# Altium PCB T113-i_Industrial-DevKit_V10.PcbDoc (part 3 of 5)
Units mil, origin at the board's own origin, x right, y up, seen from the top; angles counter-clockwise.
Board outline 4212.61 x 3188.98 mil, 4 copper layers (Top Layer, GND, PWR, Bottom Layer); 249 components, 236 nets, 911 pads, 571 vias.
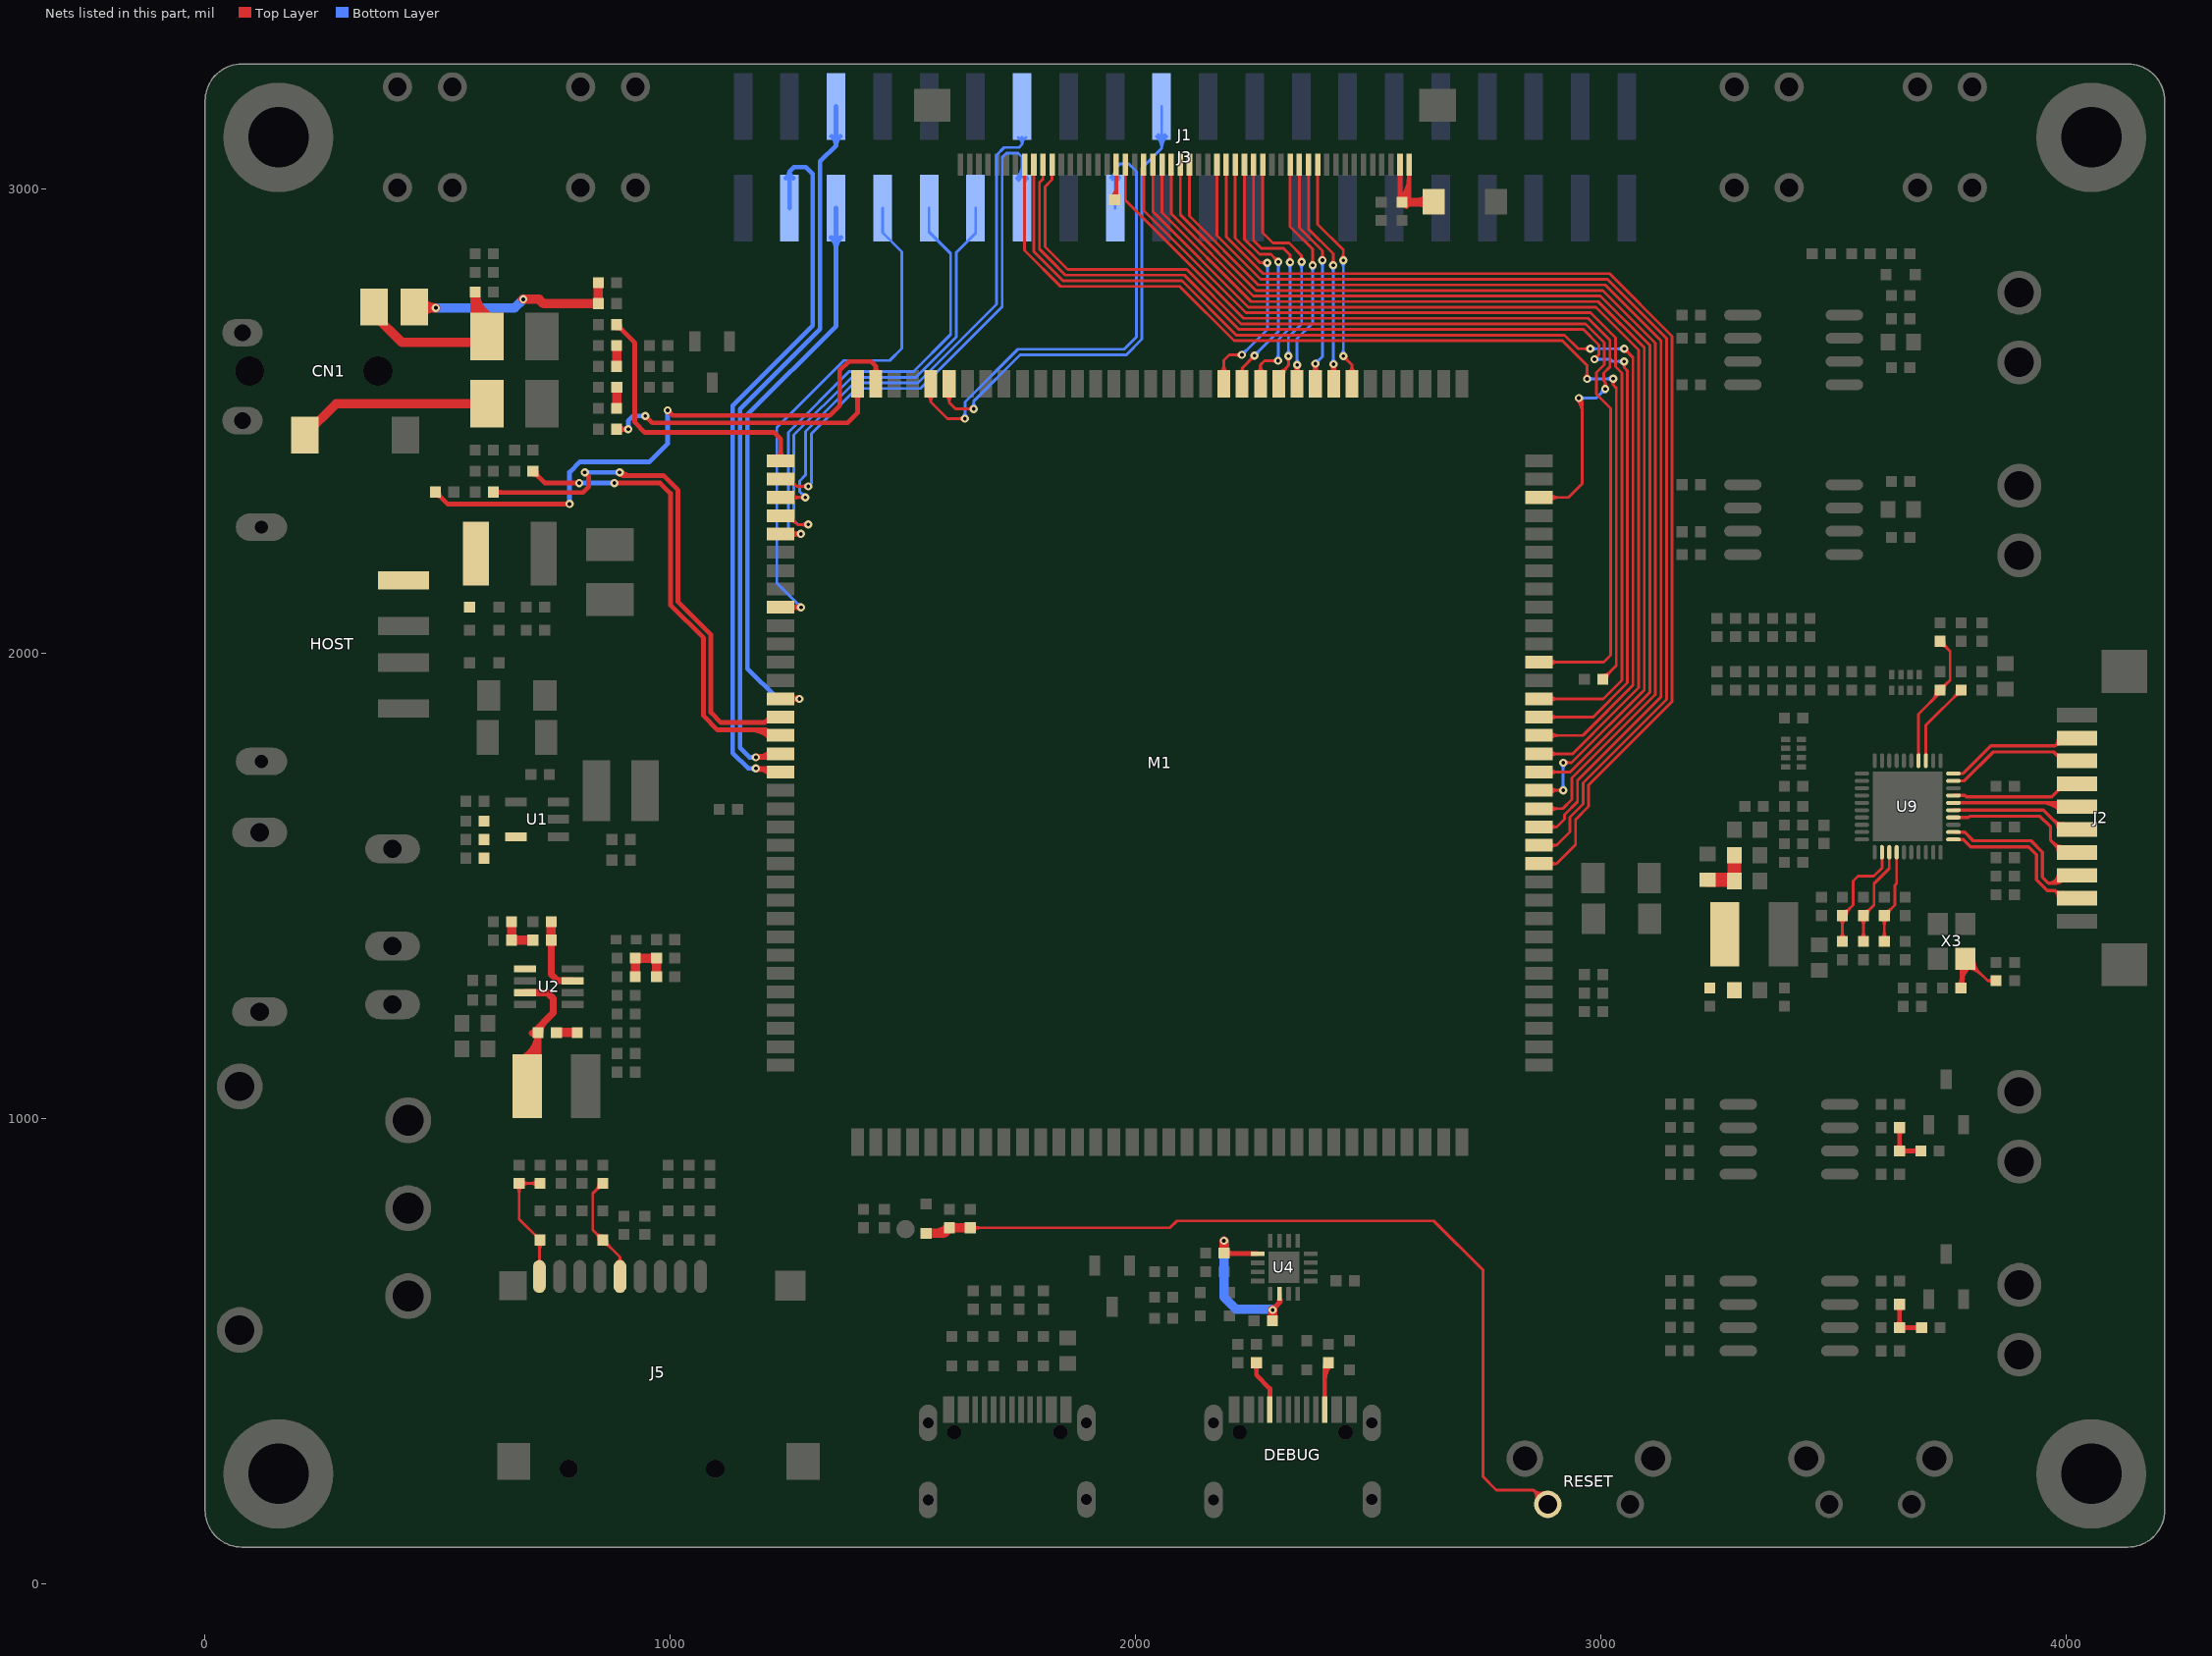
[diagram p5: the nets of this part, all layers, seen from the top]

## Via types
v1: diameter 17.72, hole 7.87, Top Layer to Bottom Layer, tented both sides, 571 vias

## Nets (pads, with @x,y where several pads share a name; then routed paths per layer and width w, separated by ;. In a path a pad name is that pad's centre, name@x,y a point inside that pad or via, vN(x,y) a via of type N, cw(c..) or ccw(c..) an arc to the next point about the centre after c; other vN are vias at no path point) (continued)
LCD_D4: J1.11 M1.109 | length 640.3
  Top Layer w6: J1.11@2389.68,3031.25 cw(c2384.72,3026.29) 2391.73,3026.29 cw(c2398.75,3026.29) J1.11@2393.79,3031.25 ; J1.11@2391.73,3051.03 2391.73,2923.2 2446.78,2868.16 v1(2446.78,2845.7) ; v1@2442.63,2849.84 ccw(c2432.63,2859.84) 2446.78,2859.84 ccw(c2460.92,2859.84) v1@2450.92,2849.84 ; v1@2446.73,2633.78 cw(c2446.73,2619.63) 2456.73,2629.64 cw(c2466.73,2639.64) v1@2452.58,2639.64 ; v1(2446.73,2639.64) 2465.55,2620.81 ; M1.109@2458.12,2603.48 ccw(c2441.63,2620.81) 2465.55,2620.81 ; M1.109@2465.55,2579.92 2465.55,2620.81 ; M1.109@2472.98,2603.48 cw(c2489.48,2620.81) 2465.55,2620.81
  Bottom Layer w6: v1@2442.58,2643.78 ccw(c2432.46,2653.9) 2446.78,2653.9 ; v1@2442.63,2841.56 cw(c2432.63,2831.56) 2446.78,2831.56 cw(c2460.92,2831.56) v1@2450.92,2841.56 ; v1@2446.78,2639.64 v1(2446.78,2845.7) ; 2446.78,2653.66 ccw(c2460.75,2653.66) v1@2450.87,2643.78
LCD_D5: J1.12 M1.110 | length 674.1
  Top Layer w6: J1.12@2369.99,3031.25 cw(c2365.03,3026.29) 2372.04,3026.29 cw(c2379.06,3026.29) J1.12@2374.1,3031.25 ; J1.12@2372.04,3051.03 2372.04,2912.65 2425.09,2859.61 v1(2425.09,2835.03) ; M1.110@2418.56,2603.29 ccw(c2401.65,2620.2) v1@2425.56,2620.2 ; v1@2420.81,2618.97 cw(c2411.44,2612.19) M1.110@2422.61,2609.2 ; v1@2420.94,2839.18 ccw(c2410.94,2849.18) 2425.09,2849.18 ccw(c2439.23,2849.18) v1@2429.23,2839.18 ; v1@2421.42,2618.26 cw(c2411.42,2608.26) 2425.56,2608.26 cw(c2439.7,2608.26) v1@2429.7,2618.26 ; v1@2422.78,2617.25 cw(c2416.67,2605.94) 2429.08,2609.27 cw(c2441.49,2612.6) v1@2430.55,2619.33 ; 2422.81,2609.93 cw(c2434.59,2606.77) v1@2428.49,2617.33 ; M1.110@2426.18,2579.92 2425.56,2580.54 v1(2425.56,2622.41) ccw(c2451.83,2622.4) M1.110@2433.64,2603.45
  Bottom Layer w6: v1@2420.94,2830.89 cw(c2410.94,2820.89) 2425.09,2820.89 cw(c2439.23,2820.89) v1@2429.23,2830.89 ; v1@2421.42,2626.55 ccw(c2412.56,2635.4) 2425.09,2635.4 ; 2425.09,2637.69 ccw(c2440.85,2637.69) v1@2429.7,2626.55 ; v1(2425.09,2835.03) 2425.09,2622.88 v1(2425.56,2622.41)
LCD_D6: J1.13 M1.111 | length 674.1
  Top Layer w6: J1.13@2350.31,3031.25 cw(c2345.35,3026.29) 2352.36,3026.29 cw(c2359.38,3026.29) J1.13@2354.42,3031.25 ; J1.13@2352.36,3051.03 2352.36,2915.36 2401.86,2865.87 v1(2401.86,2845.86) v1@2401.86,2844.16 ; M1.111@2379.19,2603.29 ccw(c2360.79,2621.69) 2386.81,2621.69 ccw(c2412.84,2621.69) M1.111@2394.43,2603.29 ; v1@2381.82,2620.06 cw(c2371.25,2612.92) 2383.57,2609.62 ; v1@2382.53,2619.2 cw(c2372.21,2608.87) M1.111@2386.81,2608.87 ; v1@2383.75,2618.27 cw(c2377.18,2606.9) 2389.86,2610.3 ; 2383.9,2610.84 cw(c2395.72,2607.67) v1@2389.61,2618.27 ; M1.111@2386.81,2588.63 v1@2386.81,2623.34 ; 2386.81,2609.53 cw(c2400.49,2609.53) v1@2390.82,2619.2 ; M1.111@2390.16,2609.18 cw(c2404.17,2612.93) v1@2391.71,2620.35 ; v1@2397.71,2850 ccw(c2387.71,2860) 2401.86,2860 ccw(c2416,2860) v1@2406,2850
  Bottom Layer w6: v1(2386.68,2623.34) 2401.86,2638.52 v1(2401.86,2845.86) ; v1@2386.68,2629.2 ccw(c2386.68,2643.35) 2396.68,2633.34 ccw(c2406.68,2623.34) v1@2392.53,2623.34 ; v1@2397.71,2841.72 cw(c2387.71,2831.71) 2401.86,2831.71 cw(c2416,2831.71) v1@2406,2841.72
LCD_D7: J1.14 M1.112 | length 678
  Top Layer w6: J1.14@2330.62,3031.25 cw(c2325.66,3026.29) 2332.67,3026.29 cw(c2339.69,3026.29) J1.14@2334.73,3031.25 ; J1.14@2332.67,3051.03 2332.67,2918.08 2380.88,2869.88 v1(2380.88,2834.8) ; M1.112@2340.06,2603.52 ccw(c2323.98,2620.63) v1(2347.45,2620.63) ; v1@2342.74,2617.14 cw(c2334.97,2611.39) 2344.31,2608.89 cw(c2353.65,2606.39) v1@2349.79,2615.26 ; v1@2343.31,2616.48 cw(c2333.31,2606.48) 2347.45,2606.48 cw(c2361.6,2606.48) v1@2351.6,2616.48 ; v1@2345.11,2615.26 cw(c2341.21,2606.34) 2350.61,2608.86 cw(c2360,2611.38) v1@2352.17,2617.15 ; M1.112@2347.44,2579.92 v1(2347.45,2620.63) ; M1.112@2354.84,2603.51 cw(c2370.98,2620.63) v1(2347.45,2620.63) ; v1@2376.73,2838.94 ccw(c2366.73,2848.94) 2380.88,2848.94 ccw(c2395.02,2848.94) v1@2385.02,2838.94
  Bottom Layer w6: v1@2343.31,2624.77 ccw(c2333.31,2634.77) 2347.45,2634.77 ccw(c2361.6,2634.77) v1@2351.6,2624.77 ; v1(2347.45,2620.63) 2347.45,2676.92 2380.88,2710.35 v1(2380.88,2834.8) ; v1@2376.73,2830.65 cw(c2366.73,2820.65) 2380.88,2820.65 cw(c2395.02,2820.65) v1@2385.02,2830.65
LCD_D10: J1.17 M1.113 | length 680
  Top Layer w6: J1.17@2271.57,3031.25 cw(c2266.61,3026.29) 2273.62,3026.29 cw(c2280.64,3026.29) J1.17@2275.68,3031.25 ; J1.17@2273.62,3051.03 2273.62,2905.07 2295.39,2883.3 2330,2883.3 2357.05,2856.25 ; M1.113@2308.07,2606.18 2315.24,2606.18 2328.97,2619.91 2328.97,2643.76 v1@2328.87,2643.87 ; M1.113@2308.07,2606.45 ccw(c2308.07,2624.4) 2320.76,2611.71 ; M1.113@2312.85,2595.67 cw(c2332.46,2595.67) 2318.59,2609.54 ; M1.113@2318.85,2595.67 cw(c2352.95,2595.67) 2328.84,2619.78 ; v1@2324.72,2635.86 cw(c2314.47,2625.6) 2328.97,2625.6 ; 2328.97,2626.11 cw(c2342.76,2626.11) v1@2333.01,2635.86 ; v1@2352.95,2846.44 ccw(c2343.29,2856.25) 2357.06,2856.25 ; v1(2357.05,2842.26) 2357.05,2856.25 ; v1@2361.16,2846.44 cw(c2370.82,2856.25) 2357.05,2856.25
  Bottom Layer w6: v1@2324.72,2644.14 ccw(c2314.72,2654.14) 2328.87,2654.14 ccw(c2343.01,2654.14) v1@2333.01,2644.14 ; v1@2328.87,2643.87 2328.87,2680.15 2357.05,2708.33 v1(2357.05,2842.26) ; v1@2352.91,2838.12 cw(c2342.91,2828.12) 2357.05,2828.12 cw(c2371.2,2828.12) v1@2361.2,2838.12
  other v1: 2328.87,2640
LCD_D11: J1.18 M1.114 | length 694.4
  Top Layer w6: J1.18@2251.88,3031.25 cw(c2246.92,3026.29) 2253.93,3026.29 cw(c2260.95,3026.29) J1.18@2255.99,3031.25 ; J1.18@2253.93,3051.03 2253.93,2888.2 2270.84,2871.3 2318.06,2871.3 2332.28,2857.08 v1(2332.28,2841.55) ; M1.114@2261.26,2603.47 ccw(c2244.65,2620.86) 2268.7,2620.86 ; M1.114@2268.7,2598.96 2268.7,2620.86 ; M1.114@2276.14,2603.47 cw(c2292.75,2620.86) 2268.7,2620.86 ; v1@2302.62,2625.52 ccw(c2292.62,2615.52) 2292.62,2629.66 ccw(c2292.62,2643.8) v1@2302.62,2633.8 ; v1(2306.76,2629.66) 2277.5,2629.66 2268.7,2620.86 ; v1@2328.14,2845.69 ccw(c2318.14,2855.69) 2332.28,2855.69 ccw(c2346.43,2855.69) v1@2336.43,2845.69
  Bottom Layer w6: v1@2302.62,2633.8 ccw(c2292.62,2643.8) 2306.76,2643.8 ccw(c2320.9,2643.8) v1@2310.9,2633.8 ; v1(2306.76,2629.66) 2306.76,2648.59 2306.76,2675.01 2332.28,2700.53 v1(2332.28,2841.55) ; v1@2328.14,2837.41 cw(c2318.14,2827.41) 2332.28,2827.41 cw(c2346.43,2827.41) v1@2336.43,2837.41
LCD_D12: J1.19 M1.115 | length 653
  Top Layer w6: M1.115@2224.19,2605.14 ccw(c2219.09,2614.52) 2229.76,2614.52 ; M1.115@2229.76,2597.7 2229.76,2614.52 ; J1.19@2232.2,3031.25 cw(c2227.24,3026.29) 2234.25,3026.29 cw(c2241.27,3026.29) J1.19@2236.31,3031.25 ; J1.19@2234.25,3051.03 2234.25,2890.91 2266.67,2858.5 2291.27,2858.5 v1(2307.18,2842.59) ; M1.115@2235.12,2604.76 cw(c2241.32,2614.52) 2229.76,2614.52 ; v1@2250.16,2640.77 cw(c2236.01,2640.77) 2246.01,2630.77 cw(c2256.01,2620.77) v1@2256.01,2634.91 ; v1(2256.01,2640.77) 2229.76,2614.52 ; v1@2301.32,2842.59 ccw(c2287.18,2842.59) 2297.18,2852.59 ccw(c2307.18,2862.59) v1@2307.18,2848.45
  Bottom Layer w6: v1(2256.01,2640.77) 2256.01,2641.24 2307.18,2692.4 v1(2307.18,2842.59) ; v1@2256.01,2646.63 ccw(c2256.01,2659.65) 2265.22,2650.45 ; v1@2261.87,2640.77 cw(c2277.13,2640.77) 2266.34,2651.56 ; v1@2303.04,2838.45 cw(c2293.04,2828.45) 2307.18,2828.45 cw(c2321.33,2828.45) v1@2311.33,2838.45
LCD_D13: J1.20 M1.116 | length 704.4
  Top Layer w6: M1.116@2182.34,2603.29 ccw(c2163.94,2621.69) 2189.96,2621.69 ccw(c2215.98,2621.69) M1.116@2197.58,2603.29 ; M1.116@2189.96,2579.92 2189.96,2630.85 2201.49,2642.38 v1(2228.75,2642.38) ; J1.20@2212.51,3031.25 cw(c2207.55,3026.29) 2214.56,3026.29 cw(c2221.58,3026.29) J1.20@2216.62,3031.25 ; J1.20@2214.56,3051.03 2214.56,2893.63 2267.83,2840.37 v1(2283.57,2840.37) ; v1@2224.61,2638.23 ccw(c2214.61,2628.23) 2214.61,2642.38 ccw(c2214.61,2656.52) v1@2224.61,2646.52 ; v1@2279.43,2836.22 ccw(c2269.43,2826.22) 2269.43,2840.37 ccw(c2269.43,2854.51) v1@2279.43,2844.51
  Bottom Layer w6: v1(2228.75,2642.38) 2283.57,2697.19 v1(2283.57,2840.37) ; v1@2228.75,2648.23 ccw(c2228.75,2662.38) 2238.75,2652.38 ccw(c2248.75,2642.38) v1@2234.61,2642.38 ; v1@2279.43,2836.22 cw(c2269.43,2826.22) 2283.57,2826.22 cw(c2297.71,2826.22) v1@2287.71,2836.22
LCD_D14: J1.21 M1.80 | length 2521.4
  Top Layer w6: J1.21@2192.83,3031.25 cw(c2187.87,3026.29) 2194.88,3026.29 cw(c2201.9,3026.29) J1.21@2196.94,3031.25 ; J1.21@2194.88,3051.03 2194.88,2896.34 2274.3,2816.92 3019.57,2816.92 3153.75,2682.74 3153.75,1896.79 2974.43,1717.46 2974.43,1671.5 2946.17,1643.24 2946.17,1589.02 2905.58,1548.43 ; M1.80@2867.13,1548.43 2905.58,1548.43 ; M1.80@2891.23,1541.61 cw(c2905.57,1529.91) 2905.57,1548.43 ; M1.80@2891.23,1555.24 ccw(c2905.57,1566.94) 2905.57,1548.43
LCD_D15: J1.22 M1.81 | length 2480.4
  Top Layer w6: J1.22@2173.14,3031.25 cw(c2168.18,3026.29) 2175.19,3026.29 cw(c2182.21,3026.29) J1.22@2177.25,3031.25 ; J1.22@2175.19,3051.03 2175.19,2898.84 2269.12,2804.92 3014.6,2804.92 3141.75,2677.77 3141.75,1901.76 2962.43,1722.43 2962.43,1676.47 2934.17,1648.21 2934.17,1616.39 2905.58,1587.8 ; M1.81@2867.13,1587.8 2905.58,1587.8 ; M1.81@2891.23,1580.98 cw(c2905.57,1569.28) 2905.57,1587.8 ; M1.81@2891.23,1594.61 ccw(c2905.57,1606.31) 2905.57,1587.8
LCD_D18: J1.25 M1.82 | length 2455.9
  Top Layer w6: J1.25@2114.09,3031.25 cw(c2109.13,3026.29) 2116.14,3026.29 cw(c2123.16,3026.29) J1.25@2118.2,3031.25 ; J1.25@2116.14,3051.03 2116.14,2940.92 2264.14,2792.92 3009.63,2792.92 3129.75,2672.8 3129.75,1906.73 2950.43,1727.4 2950.43,1681.44 2922.17,1653.18 2922.17,1643.65 2905.68,1627.17 ; M1.82@2867.13,1627.17 2905.68,1627.17 ; M1.82@2891.2,1620.32 cw(c2905.68,1608.42) 2905.68,1627.17 ; M1.82@2891.2,1634.01 ccw(c2905.68,1645.91) 2905.68,1627.17
LCD_D19: J1.26 M1.83 | length 2430.1
  Top Layer w6: J1.26@2094.4,3031.25 cw(c2089.44,3026.29) 2096.45,3026.29 cw(c2103.47,3026.29) J1.26@2098.51,3031.25 ; J1.26@2096.45,3051.03 2096.45,2943.57 2259.1,2780.92 3004.66,2780.92 3117.75,2667.83 3117.75,1911.7 2938.43,1732.37 2938.43,1686.41 2918.55,1666.54 M1.83@2867.13,1666.54 ; M1.83@2890.5,1658.91 cw(c2908.9,1640.51) 2908.9,1666.54 cw(c2908.9,1692.56) M1.83@2890.5,1674.16
LCD_D20: J1.27 M1.85 | length 2359.2
  Top Layer w6: J1.27@2074.72,3031.25 cw(c2069.76,3026.29) 2076.77,3026.29 cw(c2083.79,3026.29) J1.27@2078.83,3031.25 ; J1.27@2076.77,3051.03 2076.77,2945.69 2253.54,2768.92 2999.69,2768.92 3105.75,2662.86 3105.75,1916.67 2934.36,1745.28 M1.85@2867.13,1745.28 ; M1.85@2890.5,1737.65 cw(c2908.9,1719.25) 2908.9,1745.28 cw(c2908.9,1771.3) M1.85@2890.5,1752.9
LCD_D21: J1.28 M1.84 | length 2487.4
  Top Layer w6: J1.28@2055.03,3031.25 cw(c2050.07,3026.29) 2057.08,3026.29 cw(c2064.1,3026.29) J1.28@2059.14,3031.25 ; J1.28@2057.08,3051.03 2057.08,2948.21 2248.37,2756.92 2994.72,2756.92 3093.75,2657.89 3093.75,1921.64 2937.48,1765.37 v1(2919.56,1765.37) ; M1.84@2867.13,1705.91 2867.33,1706.11 v1(2919.56,1706.11) ; M1.84@2890.5,1698.28 cw(c2909.39,1679.39) 2909.39,1706.11 ; M1.84@2890.5,1713.53 ccw(c2908.4,1731.43) 2908.4,1706.11 ; v1@2915.42,1701.97 ccw(c2905.41,1691.96) 2905.41,1706.11 ccw(c2905.42,1720.25) v1@2915.42,1710.25 ; v1@2923.7,1761.23 cw(c2933.7,1751.23) 2933.7,1765.37 cw(c2933.7,1779.51) v1@2923.7,1769.51
  Bottom Layer w6: v1@2915.42,1710.25 ccw(c2905.42,1720.25) 2919.56,1720.25 ccw(c2933.7,1720.25) v1@2923.7,1710.25 ; v1@2915.42,1761.23 cw(c2905.42,1751.23) 2919.56,1751.23 cw(c2933.7,1751.23) v1@2923.7,1761.23 ; v1(2919.56,1706.11) v1(2919.56,1765.37)
LCD_D22: J1.29 M1.86 | length 2319.9
  Top Layer w6: J1.29@2035.35,3031.25 cw(c2030.39,3026.29) 2037.4,3026.29 cw(c2044.42,3026.29) J1.29@2039.46,3031.25 ; J1.29@2037.4,3051.03 2037.4,2950.23 2242.71,2744.92 2989.74,2744.92 3081.75,2652.92 3081.75,1926.73 3030.98,1875.96 3030.98,1875.84 2939.79,1784.65 M1.86@2867.13,1784.65 ; M1.86@2890.5,1777.02 cw(c2908.9,1758.62) 2908.9,1784.65 cw(c2908.9,1810.67) M1.86@2890.5,1792.27
LCD_D23: J1.30 M1.89 | length 2214.9
  Top Layer w6: J1.30@2015.66,3031.25 cw(c2010.7,3026.29) 2017.71,3026.29 cw(c2024.73,3026.29) J1.30@2019.77,3031.25 ; J1.30@2017.71,3051.03 2017.71,2952.86 2237.65,2732.92 2978.17,2732.92 3032.07,2679.03 3032.07,2616.83 3045.75,2603.15 3045.75,1942.84 3005.67,1902.76 M1.89@2867.13,1902.76 ; M1.89@2890.5,1895.13 cw(c2908.9,1876.73) 2908.9,1902.76 cw(c2908.9,1928.78) M1.89@2890.5,1910.38
LCD_DE: J1.40 M1.91 | length 2375.1
  Top Layer w6: J1.40@1818.81,3031.25 cw(c1813.85,3026.29) 1820.86,3026.29 cw(c1827.88,3026.29) J1.40@1822.92,3031.25 ; J1.40@1820.86,3051.03 1820.86,3019.12 1805.49,3003.74 1805.49,2874.84 1854.42,2825.91 2110.15,2825.91 2227.13,2708.92 2968.02,2708.92 3008.07,2668.87 3008.07,2621.33 2991.15,2604.41 2991.15,2557.81 3021.75,2527.21 3021.75,1996.75 3006.5,1981.5 M1.91@2867.13,1981.5 ; M1.91@2890.5,1973.87 cw(c2908.9,1955.47) 2908.9,1981.5 cw(c2908.9,2007.52) M1.91@2890.5,1989.12
LCD_HSYNC: J1.42 M1.87 | length 2662
  Top Layer w6: J1.42@1779.44,3031.25 cw(c1774.48,3026.29) 1781.49,3026.29 cw(c1788.51,3026.29) J1.42@1783.55,3031.25 ; J1.42@1781.49,3051.03 1781.49,2864.56 1844.15,2801.91 2100.02,2801.91 2217,2684.92 2922.61,2684.92 2952.06,2655.47 v1(2977.64,2655.47) ; M1.87@2867.13,1824.02 2961.95,1824.02 3069.75,1931.81 3069.75,2636.72 v1(3051,2655.47) ; M1.87@2890.5,1816.39 cw(c2908.9,1797.99) 2908.9,1824.02 cw(c2908.9,1850.04) M1.87@2890.5,1831.64 ; v1@2973.49,2651.33 ccw(c2963.49,2641.33) 2963.49,2655.47 ccw(c2963.49,2669.61) v1@2973.49,2659.61 ; v1@3051,2649.61 cw(c3051,2635.47) 3061,2645.47 cw(c3071,2655.47) v1@3056.86,2655.47
  Bottom Layer w6: v1(2977.64,2655.47) v1(3051,2655.47) ; v1@2981.78,2651.33 cw(c2991.78,2641.33) 2991.78,2655.47 cw(c2991.78,2669.61) v1@2981.78,2659.61 ; v1@3046.86,2651.33 ccw(c3036.86,2641.33) 3036.86,2655.47 ccw(c3036.86,2669.61) v1@3046.86,2659.61
LCD_PCLK: J1.43 R67.1 | length 2378.5
  Top Layer w6: J1.43@1759.76,3031.25 cw(c1754.8,3026.29) 1761.81,3026.29 cw(c1768.83,3026.29) J1.43@1763.87,3031.25 ; J1.43@1761.81,3051.03 1761.81,2867 1839.05,2789.76 2095.19,2789.76 2212.03,2672.92 2917.64,2672.92 2970.87,2619.69 v1(2970.87,2590.63) ; v1@2966.73,2594.77 ccw(c2956.73,2604.77) 2970.87,2604.77 ccw(c2985.01,2604.77) v1@2975.01,2594.77 ; R67.1@3004.68,1945 3033.75,1974.07 3033.75,2571.21 3027,2577.96 ; R67.1@3004.68,1953.81 ccw(c3004.68,1975.08) 3019.73,1960.04 ccw(c3034.77,1945) R67.1@3013.5,1945 ; v1@3022.68,2591 v1@3027,2586.67 ; v1@3023.11,2586.62 cw(c3015.42,2577.96) 3027,2577.96 ; v1(3027,2591) v1@3027,2586.67 ; v1@3030.89,2586.62 ccw(c3038.58,2577.96) 3027,2577.96 ; 3027,2577.96 v1@3027,2586.67
  Bottom Layer w6: v1@2970.77,2590.63 v1(2970.87,2590.63) 2971.24,2591 v1(3027,2591) ; v1@2975.01,2586.49 cw(c2985.89,2575.61) 2985.89,2591 ; v1@2975.01,2594.77 ccw(c2984.14,2603.9) 2984.14,2591 ; v1@3022.86,2586.85 ccw(c3012.86,2576.85) 3012.86,2591 ccw(c3012.86,2605.14) v1@3022.86,2595.14
LCD_PWM: J1.32 M1.100 | length 1892.4
  Top Layer w6: J1.32@1976.29,3031.25 cw(c1971.33,3026.29) 1978.34,3026.29 cw(c1985.36,3026.29) J1.32@1980.4,3031.25 ; J1.32@1978.34,3051.03 1978.34,2974.68 2232.11,2720.92 2973.11,2720.92 3020.07,2673.96 3020.07,2616.36 3006.75,2603.04 3006.75,2586.09 3010,2582.84 ; M1.100@2867.13,2335.83 2931.07,2335.83 2960.42,2365.18 2960.42,2542.19 ; M1.100@2890.5,2328.21 cw(c2908.9,2309.8) 2908.9,2335.83 cw(c2908.9,2361.85) M1.100@2890.5,2343.45 ; v1@2949.02,2545.31 cw(c2921.49,2517.78) 2960.42,2517.78 ; v1(2953.16,2549.45) 2960.42,2542.19 ; v1@2953.26,2549.55 cw(c2935.98,2532.27) 2960.42,2532.27 ; v1@2954.62,2543.78 cw(c2956.13,2537.9) 2960.42,2542.19 ; v1@2958.83,2548 ccw(c2964.71,2546.48) 2960.42,2542.19 ; v1@3005.91,2573.16 ccw(c2996.49,2582.84) 3010,2582.84 ; v1(3010,2568.96) 3010,2582.84 ; v1@3014.09,2573.16 cw(c3023.51,2582.84) 3010,2582.84
  Bottom Layer w6: v1(2953.16,2549.45) 2990.49,2549.45 v1(3010,2568.96) ; v1@2957.3,2545.31 cw(c2967.3,2535.31) 2967.3,2549.45 cw(c2967.3,2563.6) v1@2957.3,2553.6 ; v1@3004.14,2568.96 cw(c2990,2568.96) 3000,2558.96 cw(c3010,2548.96) v1@3010,2563.1
LCD_RESET: J1.33 R70.2 | length 101.2
  Top Layer w8: R70.2@1949.48,2981.47 ccw(c1927.3,3003.65) 1958.66,3003.65 ; R70.2@1955,2975.94 1958.66,2979.61 J1.33@1958.66,3051.03
LCD_VSYNC: J1.41 M1.88 | length 2624.4
  Top Layer w6: J1.41@1799.13,3031.25 cw(c1794.17,3026.29) 1801.18,3026.29 cw(c1808.2,3026.29) J1.41@1803.24,3031.25 ; J1.41@1801.18,3051.03 1801.18,3020.43 1793.49,3012.74 1793.49,2869.87 1832.55,2830.81 ; 1832.39,2830.64 1849.12,2813.91 2104.99,2813.91 2221.97,2696.92 2962.91,2696.92 2996.07,2663.77 2996.07,2642.26 ; M1.88@2867.13,1863.39 2983.95,1863.39 3057.75,1937.18 3057.75,2608.12 3050.88,2614.99 ; M1.88@2890.5,1855.76 cw(c2908.9,1837.36) 2908.9,1863.39 cw(c2908.9,1889.41) M1.88@2890.5,1871.01 ; v1(2986.76,2632.95) 2996.07,2642.26 ; v1@2987.07,2638.8 ccw(c2987.68,2650.65) 2996.07,2642.26 ; v1@2992.61,2633.26 cw(c3004.45,2633.88) 2996.07,2642.26 ; v1@3046.95,2623.87 cw(c3038.9,2614.99) 3050.88,2614.99 ; v1(3050.88,2628.21) 3050.88,2614.99 ; v1@3054.82,2623.87 ccw(c3062.87,2614.99) 3050.88,2614.99
  Bottom Layer w6: v1(2986.76,2632.95) 3021.61,2632.95 3026.35,2628.21 v1(3050.88,2628.21) ; v1@2990.9,2628.81 cw(c3000.9,2618.81) 3000.9,2632.95 cw(c3000.9,2647.1) v1@2990.9,2637.1 ; v1@3046.74,2624.07 ccw(c3036.74,2614.07) 3036.74,2628.21 ccw(c3036.74,2642.35) v1@3046.74,2632.35
LED0/CFG_EXT: R97.1 R103.2 U9.32 | length 347.2
  Top Layer w6: R97.1@3513.77,1387.18 ccw(c3498.73,1402.22) 3520,1402.22 ccw(c3541.27,1402.22) R97.1@3526.23,1387.18 ; R103.2@3513.77,1430.34 cw(c3498.73,1415.3) 3520,1415.3 cw(c3541.27,1415.3) R103.2@3526.23,1430.34 ; R97.1@3520,1380.94 R103.2@3520,1436.57 3542.6,1459.17 3542.6,1510.72 3553.41,1521.53 3587.3,1521.53 3604.9,1539.13 U9.32@3604.9,1572.86 ; R103.2@3520,1445.39 ccw(c3520,1466.66) 3535.04,1451.62 ccw(c3550.08,1436.57) R103.2@3528.81,1436.57
LED1/CFG_LDO0: R96.1 R102.2 U9.33 | length 315.2
  Top Layer w6: R96.1@3558.77,1387.18 ccw(c3543.73,1402.22) 3565,1402.22 ccw(c3586.27,1402.22) R96.1@3571.23,1387.18 ; R102.2@3558.77,1430.34 cw(c3543.73,1415.3) 3565,1415.3 cw(c3586.27,1415.3) R102.2@3571.23,1430.34 ; R96.1@3565,1380.94 R102.2@3565,1436.57 3587.93,1459.51 3587.93,1505.19 3620.6,1537.86 U9.33@3620.6,1572.86 ; R102.2@3565,1445.39 ccw(c3565,1466.66) 3580.04,1451.62 ccw(c3595.08,1436.57) R102.2@3573.81,1436.57
LED2/CFG_LDO1: R95.1 R101.2 U9.34 | length 303.1
  Top Layer w6: R95.1@3603.77,1387.18 ccw(c3588.73,1402.22) 3610,1402.22 ccw(c3631.27,1402.22) R95.1@3616.23,1387.18 ; R101.2@3603.77,1430.34 cw(c3588.73,1415.3) 3610,1415.3 cw(c3631.27,1415.3) R101.2@3616.23,1430.34 ; R95.1@3610,1380.94 R101.2@3610,1436.57 3632.58,1459.15 3632.58,1501.97 3636.4,1505.8 U9.34@3636.4,1572.86 ; R101.2@3610,1445.39 ccw(c3610,1466.66) 3625.04,1451.62 ccw(c3640.08,1436.57) R101.2@3618.81,1436.57
LINEINL: C26.1 M1.1 | length 661
  Top Layer w10: C26.1@884.68,2700.67 cw(c884.68,2684.23) 896.31,2695.85 cw(c907.94,2707.48) C26.1@891.5,2707.48 ; C26.1@884.68,2707.48 923.72,2668.44 923.72,2497.02 945.26,2475.48 1223.34,2475.48 1237.2,2461.62 M1.1@1237.2,2414.57 ; M1.1@1231,2420.78 ccw(c1216.01,2435.76) 1237.2,2435.76 ccw(c1258.4,2435.76) M1.1@1243.41,2420.78
LINEINR: C27.1 M1.136 | length 743.9
  Top Layer w10: C27.1@884.68,2482.48 v1@909.62,2482.48 ; C27.1@889.5,2477.66 cw(c901.13,2466.04) 901.13,2482.48 cw(c901.13,2498.92) C27.1@889.5,2487.3 ; 896.57,2483.7 ccw(c899.94,2496.26) v1@907.42,2485.62 ; 896.61,2481.27 cw(c899.94,2468.84) v1@907.4,2479.33 ; 900.29,2482.48 cw(c900.29,2473.13) v1@906.91,2479.74 ; 900.35,2482.48 ccw(c900.35,2491.76) v1@906.91,2485.2 ; v1@946.06,2507.25 cw(c946.06,2497.93) 952.65,2504.52 cw(c959.23,2511.11) v1@949.92,2511.11 ; v1(946.06,2511.11) 960.95,2496.21 1381.43,2496.21 1402.56,2517.34 M1.136@1402.56,2565.66 ; M1.136@1396.35,2557.97 cw(c1381.36,2542.98) 1402.56,2542.98 cw(c1423.75,2542.98) M1.136@1408.77,2557.97
  Bottom Layer w10: v1@906.91,2485.2 ccw(c900.32,2491.78) 909.63,2491.78 ccw(c918.95,2491.78) v1@912.36,2485.2 ; v1(909.63,2482.47) 909.63,2500.45 920.29,2511.11 v1(946.06,2511.11) ; v1@943.33,2508.38 ccw(c936.75,2501.79) 936.75,2511.11 ccw(c936.75,2520.42) v1@943.33,2513.83
LINEOUTLN: J3.27 M1.2 | length 1280.4
  Top Layer w6: M1.2@1237.2,2375.2 1256.42,2375.2 1272.06,2359.56 ; M1.2@1255.12,2364.64 cw(c1258.88,2346.38) 1272.06,2359.56 ; M1.2@1263.73,2375.2 ccw(c1281.38,2375.2) 1268.9,2362.72 ; v1@1292.66,2355.42 ccw(c1282.66,2345.42) 1282.66,2359.56 ccw(c1282.66,2373.7) v1@1292.66,2363.7 ; v1(1296.8,2359.56) 1272.06,2359.56
  Bottom Layer w6: v1(1296.8,2359.56) 1303.09,2365.85 1303.09,2472.84 1400.4,2570.14 1537.69,2570.14 1713.49,2745.94 1713.49,3067.17 1722.73,3076.42 1747.63,3076.42 1756.3,3067.75 J3.27@1756.3,3025.53 ; J3.27@1744.22,3021.6 ccw(c1715.07,3050.75) 1756.3,3050.75 ccw(c1797.53,3050.75) J3.27@1768.38,3021.6 ; J3.27@1748.47,3017.36 ccw(c1729.55,3036.27) 1756.3,3036.27 ccw(c1783.05,3036.27) J3.27@1764.13,3017.36
LINEOUTLP: J3.28 M1.3 | length 1250.9
  Top Layer w6: M1.3@1237.2,2335.83 v1(1290.5,2335.85) ; M1.3@1260.57,2328.21 cw(c1279.03,2309.75) 1279.03,2335.85 ; M1.3@1260.57,2343.45 ccw(c1278.92,2361.8) 1278.92,2335.85 ; v1@1286.36,2331.71 ccw(c1276.36,2321.71) 1276.36,2335.85 ccw(c1276.36,2349.99) v1@1286.36,2339.99
  Bottom Layer w6: v1@1284.64,2335.85 ccw(c1270.5,2335.85) 1280.5,2345.85 ccw(c1290.5,2355.85) v1@1290.5,2341.71 ; v1(1290.5,2335.85) 1277.9,2348.45 1277.9,2371.01 1291.09,2384.2 1291.09,2424.99 1291.08,2477.89 1395.33,2582.14 1532.72,2582.14 1701.49,2750.91 1701.49,3072.14 1717.76,3088.42 1749.6,3088.42 1756.3,3095.12 ; J3.28@1747.85,3109.65 cw(c1739.58,3095.12) 1756.3,3095.12 ; J3.28@1756.3,3110.41 1756.3,3095.12 ; J3.28@1764.75,3109.65 ccw(c1773.02,3095.12) 1756.3,3095.12
LINEOUTRN: J3.29 M1.4 | length 1111.4
  Top Layer w6: M1.4@1237.2,2296.46 1254.87,2296.46 1273.79,2277.54 ; M1.4@1253.09,2291.68 cw(c1253.53,2276.94) M1.4@1263.96,2287.37 ; M1.4@1253.27,2285.68 cw(c1254.09,2257.84) 1273.79,2277.54 ; M1.4@1263.73,2296.46 ccw(c1285.14,2296.46) 1270,2281.32 ; v1@1292.31,2273.39 ccw(c1282.31,2263.39) 1282.31,2277.54 ccw(c1282.31,2291.68) v1@1292.31,2281.68 ; v1(1296.45,2277.54) 1273.79,2277.54
  Bottom Layer w6: 1265.5,2334.39 1265.5,2286.96 1274.93,2277.54 v1(1296.45,2277.54) ; 1265.64,2334.39 1265.64,2470.1 1389.69,2594.14 1527.75,2594.14 1614.67,2681.06 1614.67,2862.53 1656.3,2904.16 J3.29@1656.3,2957.75 ; v1@1292.31,2273.39 ccw(c1282.31,2263.39) 1282.31,2277.54 ccw(c1282.31,2291.68) v1@1292.31,2281.68
LINEOUTRP: J3.31 M1.5 | length 1137.7
  Top Layer w6: M1.5@1237.2,2257.09 1237.51,2257.39 v1(1280.87,2257.39) ; M1.5@1260.57,2249.46 cw(c1279.72,2230.32) v1@1279.72,2257.39 ; M1.5@1260.57,2264.71 ccw(c1278.24,2282.37) v1@1278.24,2257.39 ; M1.5@1266.68,2253.9 cw(c1270.45,2239.84) v1@1277.88,2252.36 ; 1266.89,2260.43 ccw(c1270.26,2273.02) v1@1277.58,2262.24 ; 1267.83,2254.21 ccw(c1264.43,2266.88) v1@1275.8,2260.32 ; 1268.62,2259.97 cw(c1265.57,2248.56) v1@1275.8,2254.46 ; v1@1276.73,2253.25 ccw(c1266.73,2243.25) 1266.73,2257.39 ccw(c1266.73,2271.54) v1@1276.73,2261.54
  Bottom Layer w6: v1@1276.73,2253.25 ccw(c1266.73,2243.25) 1266.73,2257.39 ccw(c1266.73,2271.54) v1@1276.73,2261.54 ; v1(1280.87,2257.39) 1264.72,2257.39 1253.5,2268.61 1253.5,2475.48 1384.16,2606.14 1522.78,2606.14 1602.67,2686.03 1602.67,2860.33 1556.3,2906.7 J3.31@1556.3,2957.75
LRADC: J3.33 M1.9 | length 1237.5
  Top Layer w6: M1.9@1237.2,2099.61 1281.04,2099.61 v1(1281.11,2099.54) ; M1.9@1260.57,2091.98 cw(c1278.98,2073.58) 1278.98,2099.61 cw(c1278.98,2125.63) M1.9@1260.57,2107.23 ; 1266.78,2102.87 ccw(c1270.49,2116.74) v1@1278.03,2104.52 ; 1266.8,2099.61 cw(c1266.8,2085.23) v1@1276.97,2095.4 ; 1267,2096.4 cw(c1270.49,2083.37) v1@1277.89,2094.64 ; 1267.13,2099.61 ccw(c1267.13,2113.52) v1@1276.97,2103.68 ; 1268.46,2102.43 cw(c1265.23,2090.37) v1@1276.04,2096.61 ; 1268.73,2096.86 ccw(c1265.61,2108.49) v1@1276.04,2102.47
  Bottom Layer w6: v1@1275.25,2099.54 ccw(c1261.11,2099.54) 1271.11,2109.54 ccw(c1281.11,2119.54) v1@1281.11,2105.4 ; v1(1281.11,2099.54) 1229.11,2151.54 1229.11,2486.13 1373.11,2630.14 1471.62,2630.14 1497.74,2656.25 1497.74,2864 1456.3,2905.44 J3.33@1456.3,2957.75
MBIAS: J3.35 M1.14 | length 1387.2
  Top Layer w10: M1.14@1237.2,1902.76 1277.44,1902.76 v1(1277.56,1902.63) ; M1.14@1259.16,1896.55 cw(c1274.15,1881.56) 1274.15,1902.76 cw(c1274.15,1923.95) M1.14@1259.16,1908.96 ; M1.14@1265.97,1900.56 cw(c1269.26,1888.27) v1@1275.63,1899.29 ; M1.14@1266.58,1904.78 ccw(c1269.67,1916.3) v1@1275.63,1905.98 ; 1267.95,1902.76 cw(c1267.95,1893.02) v1@1274.83,1899.91 ; 1268.54,1902.76 ccw(c1268.54,1911.65) v1@1274.83,1905.36
  Bottom Layer w10: v1@1274.83,1899.91 ccw(c1268.24,1893.32) 1268.24,1902.63 ccw(c1268.24,1911.95) v1@1274.83,1905.36 ; v1(1277.56,1902.63) 1230.71,1902.63 1165.88,1967.47 1165.88,2513.85 1356.3,2704.28 J3.35@1356.3,2957.75 ; J3.35@1345.64,2895.32 cw(c1319.9,2869.58) 1356.3,2869.58 cw(c1392.7,2869.58) J3.35@1366.96,2895.32
MDC: R76.1 U9.13 | length 216.6
  Top Layer w6: U9.13@3699.4,1769.66 3699.4,1845.98 R76.1@3775,1921.57 ; R76.1@3766.19,1921.57 cw(c3744.92,1921.57) 3759.96,1906.53 cw(c3775,1891.49) R76.1@3775,1912.76
MDI0+: J2.2 U9.1 | length 384.6
  Top Layer w7.07: U9.1@3758.4,1600.36 3779.93,1600.36 3795.82,1584.47 3919.93,1584.47 3936.92,1567.48 3936.92,1513.66 3960.18,1490.4 3976.9,1490.4 ; 3977.52,1489.78 cw(c3961.75,1474.01) J2.2@3984.05,1474.01 ; J2.2@3993.3,1485.86 cw(c3989.11,1502.61) 3976.9,1490.4 ; J2.2@4023.82,1474.01 3993.29,1474.01 3976.9,1490.4
MDI0-: J2.3 U9.2 | length 468
  Top Layer w7.07: U9.2@3762.99,1616.16 3782.62,1616.16 3801.24,1597.54 3925.34,1597.54 3949.99,1572.89 3949.99,1519.44 3962.91,1506.52 ; 3971.06,1506.52 ccw(c3971.06,1526.83) J2.3@3991.17,1523.96 ; 3979.21,1506.52 ccw(c3979.21,1525.67) J2.3@3998.17,1522.96 ; J2.3@3984.05,1523.22 cw(c3960.44,1523.21) 3977.13,1506.52 ; J2.3@3984.17,1524.96 cw(c3962.91,1527.99) 3962.91,1506.52 ; J2.3@3993.6,1511.31 ccw(c3989.73,1493.93) 3977.13,1506.52 ; J2.3@4023.82,1523.23 3993.84,1523.23 3977.13,1506.52 ; 3962.91,1506.52 3977.13,1506.52
MDI1+: J2.4 U9.4 | length 377.6
  Top Layer w7.07: U9.4@3758.4,1647.66 3790.56,1647.66 3793.19,1650.29 3944.89,1650.29 3967.3,1627.89 3967.3,1598.49 3993.35,1572.44 J2.4@4023.82,1572.44 ; 3970.44,1595.35 ccw(c3996.26,1621.17) J2.4@3996.26,1584.65 ; 3977.47,1588.32 cw(c3961.6,1572.44) J2.4@3984.05,1572.44 ; J2.4@3982.51,1583.28 ccw(c3996.26,1597.03) J2.4@3996.26,1577.58
MDI1-: J2.5 U9.5 | length 343.2
  Top Layer w7.07: U9.5@3758.4,1663.36 3952.2,1663.36 3993.92,1621.65 J2.5@4023.82,1621.65 ; 3971.41,1644.16 ccw(c3996.26,1669.01) J2.5@3996.26,1633.86 ; 3977.07,1638.5 cw(c3960.22,1621.65) J2.5@3984.05,1621.65 ; J2.5@3983.48,1632.09 ccw(c3996.26,1644.87) J2.5@3996.26,1626.79
MDI2+: J2.6 U9.6 | length 364.9
  Top Layer w7.07: U9.6@3758.4,1679.16 4015.52,1679.16 J2.6@4023.82,1670.86 ; 3946.73,1679.16 cw(c3946.73,1621.33) J2.6@3987.63,1662.22 ; 3963.8,1679.16 cw(c3963.8,1638.4) J2.6@3992.62,1667.22 ; J2.6@3980.87,1679.16 cw(c3980.87,1655.47) J2.6@3997.62,1672.22
MDI2-: J2.7 U9.7 | length 278
  Top Layer w7.07: U9.7@3758.4,1694.86 3783.46,1694.86 3786.09,1692.23 3970.01,1692.23 3997.86,1720.08 J2.7@4023.82,1720.08
MDI3+: J2.8 U9.9 | length 299.2
  Top Layer w7.07: U9.9@3758.4,1726.36 3782.05,1726.36 3844.28,1788.59 3973.94,1788.59 3993.24,1769.29 J2.8@4023.82,1769.29
MDI3-: J2.9 U9.10 | length 333.2
  Top Layer w7.07: U9.10@3758.4,1742.16 3779.37,1742.16 3838.87,1801.66 3977.39,1801.66 ; J2.9@3984.05,1818.24 cw(c3961.31,1817.75) 3977.4,1801.66 ; J2.9@3993.76,1806.54 ccw(c3990.09,1788.97) 3977.39,1801.66 ; J2.9@4023.82,1818.5 3994.23,1818.5 3977.39,1801.66
MDIO: R75.1 R87.1 U9.14 | length 407.4
  Top Layer w6: U9.14@3683.6,1769.66 3683.6,1870.18 R75.1@3732.5,1919.07 ; 3711.42,1898 ccw(c3687.85,1921.57) R75.1@3721.19,1921.57 ; 3721.67,1908.24 ccw(c3708.33,1921.57) R75.1@3727.19,1921.57 ; R75.1@3723.49,1910.07 cw(c3730,1903.56) R75.1@3730,1912.76 ; R75.1@3730,1921.57 3751.35,1942.92 3751.35,2005.23 R87.1@3730,2026.57 ; R75.1@3730,1930.39 ccw(c3730,1951.66) 3745.04,1936.62 ccw(c3760.08,1921.57) R75.1@3738.81,1921.57 ; R87.1@3730,2017.76 cw(c3730,1996.49) 3745.04,2011.53 cw(c3760.08,2026.57) R87.1@3738.81,2026.57
MIC_DET: M1.135 R20.2 | length 1379.7
  Top Layer w10: R20.2@495.31,2340.67 cw(c495.31,2324.23) 506.94,2335.85 cw(c518.57,2347.48) R20.2@502.13,2347.48 ; R20.2@495.31,2347.48 521.04,2321.75 v1(783.28,2321.75) ; v1@780.55,2319.02 ccw(c773.97,2312.44) 773.97,2321.75 ccw(c773.97,2331.07) v1@780.55,2324.48 ; v1@994.17,2519.16 cw(c994.17,2509.85) 1000.76,2516.43 cw(c1007.34,2523.02) v1@998.03,2523.02 ; v1(994.17,2523.02) 1004.97,2512.21 1343.16,2512.21 1364.04,2533.1 1364.04,2608.7 1383.74,2628.4 1431.61,2628.4 1441.93,2618.08 M1.135@1441.93,2579.92 ; M1.135@1435.72,2601.88 ccw(c1420.73,2616.87) 1441.93,2616.87 ccw(c1463.12,2616.87) M1.135@1448.14,2601.88
  Bottom Layer w10: v1@780.55,2324.48 ccw(c773.94,2331.09) 783.29,2331.09 ; v1(783.28,2321.75) 783.29,2389.91 805.74,2412.37 955.57,2412.37 994.17,2450.97 v1(994.17,2523.02) ; 783.29,2331.04 ccw(c792.57,2331.04) v1@786.01,2324.48 ; v1@991.44,2520.29 cw(c984.86,2513.7) 994.17,2513.7 cw(c1003.48,2513.7) v1@996.9,2520.29
MICIN1N: J3.23 M1.132 | length 1238
  Top Layer w6: M1.132@1553.09,2555.93 cw(c1540.51,2540.99) 1560.04,2540.99 cw(c1579.57,2540.99) M1.132@1566.99,2555.93 ; M1.132@1560.04,2579.92 1560.04,2540.99 1595.77,2505.26 v1(1633.45,2505.26) ; v1@1629.31,2501.12 ccw(c1619.31,2491.12) 1619.31,2505.26 ccw(c1619.31,2519.41) v1@1629.31,2509.41
  Bottom Layer w6: v1@1629.31,2509.41 ccw(c1619.31,2519.41) 1633.45,2519.41 ccw(c1647.6,2519.41) v1@1637.6,2509.41 ; v1(1633.45,2505.26) 1633.45,2540.9 1747.22,2654.67 1975.4,2654.67 2001.74,2681.01 2001.74,3036.75 1985.57,3052.92 1966.7,3052.92 1956.3,3042.52 ; J3.23@1946.44,3023.47 ccw(c1932.97,3042.52) 1956.3,3042.52 ; J3.23@1949.9,3018.57 ccw(c1941.16,3030.92) 1956.3,3030.92 ccw(c1971.43,3030.92) J3.23@1962.7,3018.57 ; J3.23@1956.3,2957.75 1956.3,3042.52 ; J3.23@1966.16,3023.47 cw(c1979.63,3042.52) 1956.3,3042.52
MICIN1P: J3.22 M1.131 | length 1224.4
  Top Layer w6: M1.131@1592.2,2556.16 cw(c1577.65,2539.98) 1599.41,2539.98 ; M1.131@1599.41,2579.92 1599.41,2539.98 ; M1.131@1606.62,2556.16 ccw(c1621.17,2539.98) 1599.41,2539.98 ; v1@1648.09,2521.96 ccw(c1638.09,2511.96) 1638.09,2526.1 ccw(c1638.09,2540.24) v1@1648.09,2530.24 ; v1(1652.23,2526.1) 1613.29,2526.1 1599.41,2539.98
  Bottom Layer w6: v1@1648.09,2530.24 ccw(c1638.09,2540.24) 1652.23,2540.24 ccw(c1666.37,2540.24) v1@1656.37,2530.24 ; v1(1652.23,2526.1) 1652.23,2542.71 1752.12,2642.61 1980.3,2642.61 2013.74,2676.04 2013.74,3043.97 2056.3,3086.53 ; J3.22@2044.97,3111.71 cw(c2022.65,3086.53) 2056.3,3086.53 ; J3.22@2048.95,3116.2 cw(c2034.47,3099.86) 2056.3,3099.86 cw(c2078.13,3099.86) J3.22@2063.65,3116.2 ; J3.22@2056.3,3176.26 2056.3,3086.53 ; J3.22@2067.63,3111.71 ccw(c2089.95,3086.53) 2056.3,3086.53
MICIN2N: J3.36 M1.17 | length 1698.6
  Top Layer w10: v1(1184,1777) v1@1185.6,1777 ; v1@1184.32,1775.72 v1@1185.6,1777 ; v1@1185.93,1780.34 ccw(c1191.29,1789.63) 1194.07,1779.27 ; v1@1186.73,1774.27 cw(c1193.31,1767.69) 1193.31,1777 cw(c1193.31,1786.31) v1@1186.73,1779.73 ; 1207.43,1777 ccw(c1207.43,1796.74) M1.17@1222.38,1783.85 ; M1.17@1214.81,1790.38 cw(c1185.6,1815.56) v1@1185.6,1777 ; M1.17@1237.2,1784.65 1229.56,1777 v1@1185.6,1777
  Bottom Layer w10: v1@1181.27,1774.27 ccw(c1174.69,1767.69) 1174.69,1777 ccw(c1174.69,1786.31) v1@1181.27,1779.73 ; v1(1184,1777) 1170.32,1777 1149.88,1797.45 1149.88,2525.57 1321.89,2697.59 1321.89,3058.41 1356.3,3092.82 ; J3.36@1346.79,3112.78 cw(c1330.59,3092.82) 1356.3,3092.82 ; J3.36@1356.3,3176.26 1356.3,3092.82 ; J3.36@1365.8,3112.78 ccw(c1382.01,3092.82) 1356.3,3092.82
MICIN2P: J3.37 M1.18 | length 1706.7
  Top Layer w10: v1@1185.93,1749.66 cw(c1190.59,1741.59) 1193,1750.59 ; v1@1186.73,1750.27 cw(c1193.31,1743.69) 1193.31,1753 cw(c1193.31,1762.31) v1@1186.73,1755.73 ; v1@1187.34,1754.93 ccw(c1195.41,1759.59) 1193,1750.59 ; 1206.7,1753 cw(c1206.7,1731.78) M1.18@1222.36,1746.1 ; M1.18@1214.98,1739.35 ccw(c1184,1711.03) v1(1184,1753) 1229.48,1753 M1.18@1237.2,1745.28
  Bottom Layer w10: v1@1181.27,1750.27 ccw(c1174.69,1743.69) 1174.69,1753 ccw(c1174.69,1762.31) v1@1181.27,1755.73 ; v1(1184,1753) 1167.29,1753 1133.88,1786.41 1133.88,2533.63 1305.89,2705.64 1305.89,3031.78 1291.41,3046.26 1265.68,3046.26 1256.3,3036.87 ; J3.37@1248.25,3022.27 ccw(c1239.03,3036.87) 1256.3,3036.87 ; J3.37@1256.3,2957.75 1256.3,3036.87 ; J3.37@1264.35,3022.27 cw(c1273.57,3036.87) 1256.3,3036.87
MICIN3N: C21.2 M1.16 | length 1172.5
  Top Layer w10: C21.2@704.69,2385.67 cw(c704.69,2369.23) 716.31,2380.85 cw(c727.94,2392.48) C21.2@711.5,2392.48 ; C21.2@704.69,2392.48 730.39,2366.78 v1(804.14,2366.78) ; v1@801.41,2364.05 ccw(c794.82,2357.46) 794.82,2366.78 ccw(c794.82,2376.09) v1@801.41,2369.5 ; v1(879.74,2366.78) 978.3,2366.78 1000.46,2344.62 1000.46,2104.25 1071.26,2033.45 1071.26,1866.09 1101.47,1835.88 1205.31,1835.88 ; v1@882.47,2364.05 cw(c889.05,2357.46) 889.05,2366.78 cw(c889.05,2376.09) v1@882.47,2369.51 ; 1171.62,1835.88 cw(c1171.62,1774.18) M1.16@1215.25,1817.81 ; 1195.76,1835.88 cw(c1195.76,1798.32) M1.16@1222.32,1824.88 ; M1.16@1209.5,1831.69 cw(c1201.82,1824.02) M1.16@1212.68,1824.02 ; M1.16@1217.31,1824.02 1217.17,1824.02 1205.31,1835.88 ; M1.16@1218.95,1832.43 cw(c1215.02,1845.59) 1205.31,1835.88
  Bottom Layer w10: v1(804.14,2366.78) v1(879.74,2366.78) ; v1@806.87,2364.05 cw(c813.45,2357.46) 813.45,2366.78 cw(c813.45,2376.09) v1@806.87,2369.5 ; v1@877.01,2364.05 ccw(c870.43,2357.46) 870.43,2366.78 ccw(c870.42,2376.09) v1@877.01,2369.51
MICIN3P: C22.2 M1.15 | length 1258.8
  Top Layer w10: C22.2@619.69,2347.48 620.67,2346.49 812.03,2346.49 824.41,2358.87 824.41,2381.31 v1(816.04,2389.68) ; C22.2@624.5,2342.66 cw(c633.74,2333.42) 633.74,2346.49 ; C22.2@624.5,2352.3 ccw(c638.51,2366.31) 638.51,2346.49 ; v1@816.04,2385.82 cw(c816.04,2376.5) 822.63,2383.09 cw(c829.21,2389.68) v1@819.9,2389.68 ; v1@890.96,2385.71 cw(c890.96,2376.4) 897.55,2382.98 cw(c904.14,2389.57) v1@894.82,2389.57 ; v1(890.96,2389.57) 897.76,2382.78 984.93,2382.78 1016.46,2351.24 1016.46,2111.38 1087.26,2040.58 1087.26,1873.1 1108.48,1851.88 1202.52,1851.88 ; v1@893.69,2392.3 ccw(c916.68,2415.29) 916.68,2382.78 ; M1.15@1218.28,1855.2 ccw(c1212.95,1841.46) 1202.52,1851.88 ; M1.15@1237.2,1863.39 1214.03,1863.39 1202.52,1851.88
  Bottom Layer w10: v1(816.04,2389.68) 890.86,2389.68 v1(890.96,2389.57) ; v1@818.77,2386.95 cw(c825.36,2380.36) 825.36,2389.68 cw(c825.36,2398.99) v1@818.77,2392.41 ; 881.39,2389.68 cw(c881.39,2380) v1@888.23,2386.84 ; 881.9,2389.68 ccw(c881.9,2398.63) v1@888.23,2392.3
NetC2_2: C2.2 D1.2 J1.1 J1.2 | length 414.4
  Top Layer w10: C2.2@2568.2,2975.43 ccw(c2518.99,3024.64) 2588.58,3024.64 ; 2568.89,2997.01 ccw(c2599.41,2997.01) C2.2@2577.83,2975.43 ; J1.2@2568.89,3051.03 2568.89,2974.74 C2.2@2573.02,2970.61 ; C2.2@2575.27,2968.36 ccw(c2543.13,3000.5) 2588.58,3000.5 ; C2.2@2582.34,2961.29 ccw(c2567.27,2976.36) 2588.58,2976.36 ; J1.1@2588.58,3051.03 2588.58,2971.49 2589.46,2970.61
  Top Layer w20: C2.2@2573.02,2970.61 2589.46,2970.61 2640.27,2970.61 D1.2@2641.34,2971.69 ; 2605.86,2970.61 ccw(c2605.86,3007.17) D1.2@2631.71,2981.32 ; 2611.05,2970.61 cw(c2611.05,2941.4) D1.2@2631.71,2962.06
NetC6_1: C6.1 R2.1 R3.2 U1.5
NetC8_1: C8.1 R5.2 U2.7 | length 165.4
  Top Layer w15: R5.2@743.76,1383.72 743.76,1310.66 757.91,1296.51 U2.7@790.26,1296.51
  Top Layer w20: R5.2@743.76,1383.72 C8.1@743.76,1423.72
NetC12_1: C12.1 R5.1 R6.1 U2.1 | length 85.6
  Top Layer w20: R6.1@658.76,1423.72 C12.1@658.76,1383.72 R5.1@704.39,1383.72
NetC14_1: C14.1 R9.1 | length 45.3
  Top Layer w20: C14.1@755,1185 R9.1@800.32,1185
NetC14_2: C14.2 L2.1 U2.3 | length 486.4
  Top Layer w15: L2.1@681.35,1128.9 ccw(c653.95,1184.16) 715.63,1184.16 715.63,1093.62 L2.1@692,1070 ; U2.3@687.9,1270.92 735.89,1270.92 748.46,1258.35 748.46,1227.58 705.04,1184.16 703.2,1184.16 ccw(c703.21,1197.42) C14.2@712.58,1188.05 ; L2.1@688.01,1115.46 ccw(c665.94,1159.98) 715.63,1159.98 ; L2.1@694.67,1102.02 ccw(c677.93,1135.8) L2.1@715.63,1135.8 ; C14.2@719.94,1185 cw(c753.89,1185) 729.88,1209
NetC17_2: C17.2 R8.1 R10.1 R11.2 | length 125.6
  Top Layer w20: R8.1@924.68,1305 R10.1@924.68,1345 R11.2@970.31,1345 C17.2@970.31,1305
NetC28_2: C28.2 R17.1 | length 45.1
  Top Layer w20: C28.2@884.69,2527.48 885,2527.8 R17.1@885,2572.48
NetC29_2: C29.2 R18.1 | length 45
  Top Layer w20: R18.1@884.68,2617.48 C29.2@884.69,2662.48
NetC31_2: C31.2 CN1.3 | length 420.2
  Top Layer w20: CN1.3@213.82,2469.68 281.62,2537.48 C31.2@605.9,2537.48
NetC32_2: C32.2 CN1.4 R22.2 | length 520.2
  Top Layer w20: CN1.4@363.42,2745.27 363.42,2728.37 422.9,2668.9 592.32,2668.9 C32.2@605.9,2682.48 580.31,2708.07 R22.2@580.31,2777.52 ccw(c642,2777.52) C32.2@616.44,2721.37 ; 580.31,2746.43 ccw(c627.85,2746.43) C32.2@608.15,2703.17
NetC38_2: C38.2 C39.2 U4.1 U4.6 | length 573
  Top Layer w10: C38.2@2190.35,711.22 2191.8,709.78 U4.1@2262.35,709.78 ; C38.2@2195.17,706.4 cw(c2203.32,698.26) 2203.32,709.78 ; C38.2@2195.17,716.04 ccw(c2210.28,731.14) 2210.28,709.78 ; C39.2@2289.3,570.12 ccw(c2277.68,581.74) 2294.12,581.74 ccw(c2310.56,581.74) C39.2@2298.93,570.12 ; v1@2291.39,586.74 cw(c2279.78,580.03) C39.2@2292.73,576.56 ; v1@2293.73,592.4 ccw(c2288.73,611.08) 2305.48,601.41 ; C39.2@2294.12,565.3 v1@2294.12,588.06 ; 2294.12,577.87 cw(c2305.53,577.87) v1@2297.46,585.94 ; v1@2294.49,592.52 ccw(c2293.79,603.83) 2303.61,598.16 ; v1(2294.73,588.67) 2309.59,603.53 ; v1@2294.73,592.53 ccw(c2294.73,601.84) 2301.32,595.26 ccw(c2307.9,588.67) v1@2298.59,588.67 ; 2295.25,577.51 cw(c2303.75,579.79) v1@2297.48,585.96 ; 2302.76,596.7 ccw(c2286.07,613.39) U4.6@2309.67,613.39 ; U4.6@2309.59,623.23 2309.59,603.53 ; U4.6@2309.65,613.44 cw(c2304.61,608.51) 2309.59,603.53
  Top Layer w20: v1(2190.15,737.35) 2190.15,711.42 C38.2@2190.35,711.22 ; C39.2@2294.12,565.3 2294.73,565.91 v1(2294.73,588.67)
  Bottom Layer w20: v1(2190.15,737.35) 2190.15,616.49 2216.41,590.23 v1@2294.73,590.23
NetC52_1: C52.1 R54.2 R55.1 | length 200.9
  Top Layer w10: R54.2@3637.94,555.45 ccw(c3626.31,567.07) 3642.76,567.07 ccw(c3659.2,567.07) 3647.57,555.45 ccw(c3659.2,567.07) 3659.2,550.63 ccw(c3659.2,534.19) R54.2@3647.57,545.81 ; R55.1@3637.94,595.81 cw(c3626.31,584.19) 3642.76,584.19 cw(c3659.2,584.19) R55.1@3647.57,595.81 ; R55.1@3642.76,600.63 R54.2@3642.76,550.63 C52.1@3690.32,550.63 ; C52.1@3685.5,545.81 ccw(c3673.87,534.19) 3673.87,550.63 ccw(c3673.87,567.07) C52.1@3685.5,555.45
NetC53_1: C53.1 R56.2 R57.1 | length 198.9
  Top Layer w10: R56.2@3637.94,935.45 ccw(c3626.31,947.07) 3642.76,947.07 ccw(c3659.2,947.07) 3647.57,935.45 ccw(c3659.2,947.07) 3659.2,930.63 ccw(c3659.2,914.19) R56.2@3647.57,925.81 ; R57.1@3637.94,975.81 cw(c3626.31,964.19) 3642.76,964.19 cw(c3659.2,964.19) R57.1@3647.57,975.81 ; R57.1@3642.76,980.63 R56.2@3642.76,930.63 C53.1@3688.39,930.63 ; C53.1@3683.57,925.81 ccw(c3671.94,914.19) 3671.94,930.63 ccw(c3671.94,947.07) C53.1@3683.57,935.45
NetC58_1: C58.1 D25.2 R69.1 RESET.2 | length 2012.7
  Top Layer w6: R69.1@1645,765.32 2074.13,765.32 2089.12,780.3 2641.24,780.3 2746.85,674.69 2746.85,230.25 2776.03,201.07 2856.13,201.07 ; R69.1@1651.23,759.08 cw(c1666.27,744.04) 1666.27,765.32 cw(c1666.27,786.59) R69.1@1651.23,771.55 ; RESET.2@2861.27,179.22 ccw(c2841.06,186) 2856.13,201.07 ; RESET.2@2866.95,177.31 ccw(c2851.32,182.56) 2862.98,194.22 ccw(c2874.64,205.88) RESET.2@2879.89,190.25 ; RESET.2@2877.98,195.94 cw(c2871.2,216.14) 2856.13,201.07 ; RESET.2@2886.42,170.78 2856.13,201.07
  Top Layer w20: D25.2@1550,753.5 1588.19,753.5 C58.1@1600,765.32 R69.1@1645,765.32 ; 1567.11,753.5 ccw(c1567.11,798.2) C58.1@1598.72,766.6
NetC71_1: C71.1 C73.1 L3.2 R88.1 R93.2 R94.2 | length 113.5
  Top Layer w30: R93.2@3230,1513.7 3285,1513.7 C71.1@3287.44,1511.26 R94.2@3287.44,1566.26
NetC72_1: C72.1 R89.1 X3.3 | length 529.9
  Top Layer w6: C72.1@3768.45,1287.49 ccw(c3753.41,1302.53) 3774.68,1302.53 ccw(c3795.96,1302.53) C72.1@3780.92,1287.49 ; C72.1@3770.2,1288.84 ccw(c3759.02,1307.72) 3780.27,1302.28 ; X3.3@3771.34,1328.7 cw(c3763.26,1320.63) X3.3@3774.68,1320.63 ; C72.1@3774.68,1280.47 cw(c3836.47,1280.47) X3.3@3796.58,1327.65 ; C72.1@3774.68,1281.26 3774.68,1334.01 X3.3@3784.53,1343.86 3831.82,1296.57 ; 3774.68,1293.4 cw(c3825.54,1293.4) X3.3@3792.7,1332.23 ; 3774.68,1306.33 cw(c3814.6,1306.33) X3.3@3788.83,1336.81 ; 3774.68,1319.26 cw(c3803.67,1319.26) X3.3@3784.95,1341.39 ; 3780.04,1301.36 ccw(c3799.99,1296.25) C72.1@3782.27,1285.75 ; X3.3@3784.53,1323.24 cw(c3784.53,1273.45) 3819.73,1308.66 ; X3.3@3784.53,1329.24 cw(c3784.53,1293.94) 3809.49,1318.9 ; X3.3@3797.18,1341.89 ccw(c3822.98,1341.89) X3.3@3804.74,1323.65 ; X3.3@3803.18,1341.89 ccw(c3843.46,1341.89) 3814.98,1313.41 ; R89.1@3843.08,1291.11 ccw(c3831.82,1282.22) 3831.82,1296.57 ; R89.1@3843.08,1302.04 cw(c3831.82,1310.93) 3831.82,1296.57 ; R89.1@3850,1296.57 3831.82,1296.57
NetCN1_5: CN1.5 R21.1 R24.1 | length 519.8
  Top Layer w20: CN1.5@450.04,2745.27 451.86,2743.46 v1(495.84,2743.46) cw(c495.84,2783.74) CN1.5@464.99,2757.83 ; CN1.5@463.85,2731.47 cw(c492.8,2702.51) v1@492.8,2743.46 ; v1(683.85,2761.87) 717.91,2761.87 727.29,2752.48 R21.1@845.32,2752.48 R24.1@845.32,2797.48
  Bottom Layer w20: v1(495.84,2743.46) 665.44,2743.46 v1(683.85,2761.87)
NetD4_2: D4.2 J5.9 R25.1 R29.2 | length 399.1
  Top Layer w6: R29.2@668.81,854.68 cw(c653.77,839.63) 675.04,839.63 cw(c696.31,839.63) 681.27,854.68 cw(c696.31,839.63) 696.31,860.91 cw(c696.31,882.18) R29.2@681.27,867.14 ; D4.2@713.81,732.86 cw(c702.29,721.35) 718.58,721.35 ; R25.1@713.81,854.68 ccw(c698.77,839.63) 698.77,860.91 ccw(c698.77,882.18) R25.1@713.81,867.14 ; J5.9@718.58,660.59 D4.2@718.58,737.63 ; 718.58,714.3 cw(c744.84,714.3) D4.2@726.27,732.86 ; D4.2@720.04,739.09 D4.2@718.58,737.63 ; R25.1@720.04,860.91 R29.2@675.04,860.91 675.04,784.09 718.58,740.55 D4.2@718.58,737.63
NetD12_2: D12.2 J5.5 R26.1 | length 359.9
  Top Layer w6: D12.2@846.23,739.09 ccw(c824.96,739.09) 840,754.14 ccw(c855.04,769.18) D12.2@855.04,747.91 ; R26.1@846.23,860.91 cw(c824.96,860.91) 840,845.86 cw(c855.04,830.82) R26.1@855.04,852.09 ; D12.2@855.04,730.28 cw(c855.04,709.01) 870.08,724.05 cw(c885.12,739.09) D12.2@863.85,739.09 ; R26.1@855.04,860.91 833.41,839.28 833.41,760.72 D12.2@855.04,739.09 891.81,702.32 ; J5.5@885.85,691.23 ccw(c878.5,702.32) 891.81,702.32 ; J5.5@891.81,660.59 891.81,702.32 ; J5.5@897.77,691.23 cw(c905.12,702.32) 891.81,702.32
NetD21_2: D21.2 F1.2 HOST.1
NetDEBUG_A5: DEBUG.A5 R28.1 | length 139
  Top Layer w10: R28.1@2255.18,470.5 cw(c2243.56,458.87) 2260,458.87 cw(c2276.44,458.87) R28.1@2264.82,470.5 ; R28.1@2260,475.32 2260,448.65 2288.98,419.66 DEBUG.A5@2288.98,374.13
NetDEBUG_B5: DEBUG.B5 R27.1 | length 153.7
  Top Layer w10: DEBUG.B5@2407.09,374.13 2407.09,467.41 R27.1@2415,475.32 ; 2407.09,439.79 cw(c2450.53,439.79) R27.1@2419.82,470.5 ; R27.1@2407.09,463.93 cw(c2426.39,463.93) R27.1@2412.75,477.57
